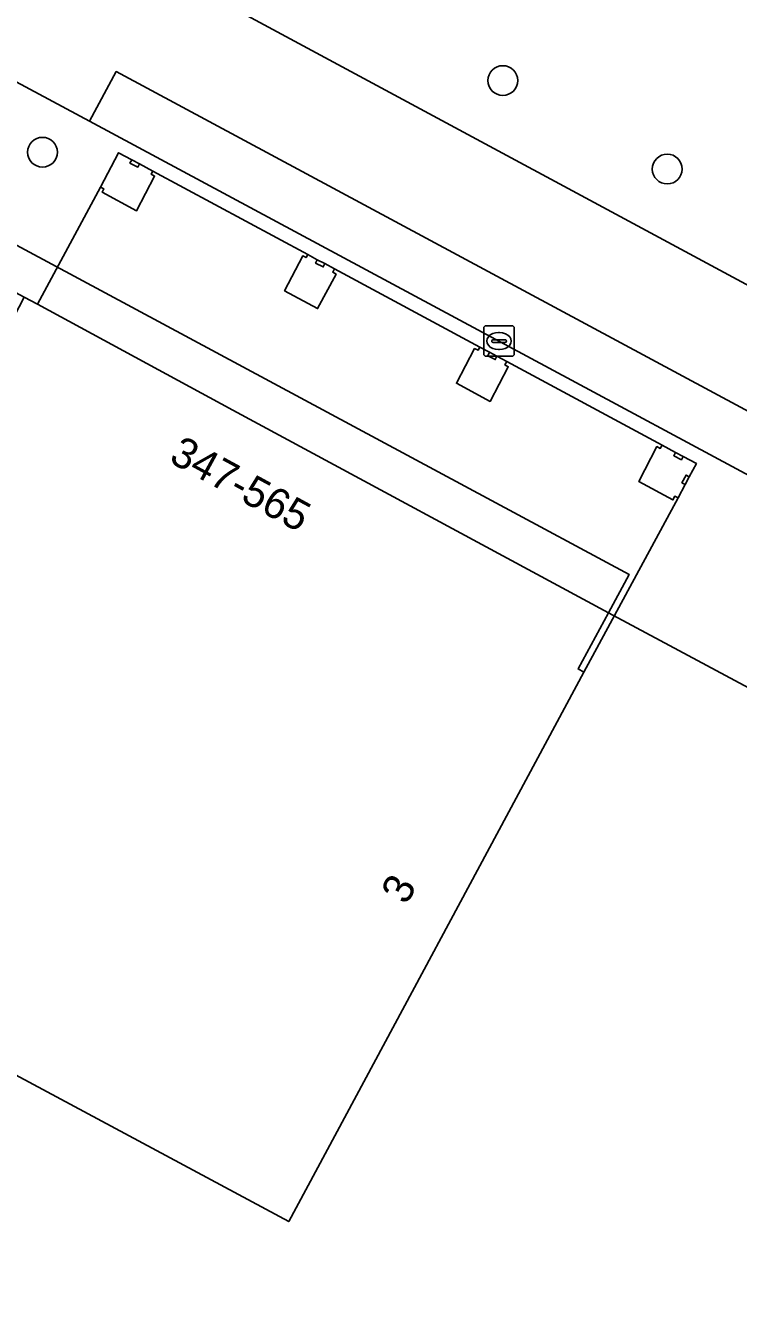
# Model space of a CAD drawing. Extents: x 159489 to 160304, y 383825 to 384531.
# Drawn here: x 159556.82 to 159580.19, y 384258.57 to 384300.92 of the extents above; entities that cross this region are included whole.
import ezdxf

# ---------------------------------------------------------------- set-up
doc = ezdxf.new("R2010")
doc.units = 0
for name, color, linetype in [('IMGEO_Boom', 7, 'Continuous'), ('IMGEO_Erf', 7, 'Continuous'), ('IMGEO_Groenvoorziening', 7, 'Continuous'), ('IMGEO_Kolk', 7, 'Continuous'), ('IMGEO_Pand', 7, 'Continuous'), ('IMGEO_Pand_nummerreeks', 7, 'Continuous'), ('IMGEO_Pand_overbouw', 7, 'Continuous'), ('IMGEO_Parkeervlak_gesloten', 7, 'Continuous'), ('IMGEO_Rijbaan_lokaal_gesloten', 7, 'Continuous'), ('IMGEO_Voetpad_open', 7, 'Continuous')]:
    doc.layers.add(name, color=color, linetype=linetype)

msp = doc.modelspace()

# ---------------------------------------------------------------- linework, layer by layer
at = {"layer": 'IMGEO_Boom'}
for centre in [(159572.468, 384299.119), (159557.37, 384296.767), (159577.86, 384296.215)]:
    msp.add_circle(centre, 0.489, dxfattribs=at)
at = {"layer": 'IMGEO_Erf'}
msp.add_lwpolyline([(159631.56, 384209.476), (159640.276, 384225.681), (159611.777, 384241.285), (159616.379, 384249.69), (159600.425, 384258.245), (159593.348, 384245.049), (159582.491, 384250.872), (159578.85, 384252.831), (159587.23, 384268.419), (159590.223, 384274), (159575.933, 384281.657), (159574.935, 384279.809), (159575.127, 384279.7), (159565.449, 384261.675), (159556.176, 384266.653), (159554.827, 384264.14), (159546.454, 384248.546), (159558.913, 384230.144), (159558.499, 384229.864), (159559.363, 384228.538), (159560.934, 384226.137), (159561.341, 384226.407), (159569.144, 384213.675)], dxfattribs=at)
at = {"layer": 'IMGEO_Groenvoorziening'}
msp.add_lwpolyline([(159534.827, 384332.312), (159520.929, 384324.852), (159521.207, 384324.29), (159525.025, 384322.248), (159542.586, 384312.826), (159546.562, 384310.695), (159582.424, 384291.365), (159580.802, 384307.588)], dxfattribs=at)
at = {"layer": 'IMGEO_Kolk'}
for p, q in [((159571.918, 384291.071), (159572.77, 384291.071)), ((159571.843, 384290.145), (159571.843, 384290.997)), ((159572.145, 384290.614), (159572.543, 384290.614)), ((159572.331, 384290.851), (159572.356, 384290.851)), ((159572.844, 384290.997), (159572.844, 384290.145)), ((159572.102, 384290.565), (159572.102, 384290.577)), ((159572.54, 384290.528), (159572.142, 384290.528)), ((159572.354, 384290.291), (159572.329, 384290.291)), ((159572.586, 384290.577), (159572.586, 384290.565)), ((159572.77, 384290.071), (159571.918, 384290.071))]:
    msp.add_line(p, q, dxfattribs=at)
for points in [[(159571.918, 384291.071), (159572.77, 384291.071)], [(159571.843, 384290.145), (159571.843, 384290.997)], [(159572.844, 384290.997), (159572.844, 384290.145)], [(159572.77, 384290.071), (159571.918, 384290.071)]]:
    msp.add_lwpolyline(points, dxfattribs=at)
for centre, radius, start, end in [((159571.92, 384290.995), 0.0765, 91.552, 178.448), ((159571.92, 384290.995), 0.0765, 91.552, 178.448), ((159572.768, 384290.995), 0.0765, 1.552, 88.448), ((159572.768, 384290.995), 0.0765, 1.552, 88.448), ((159572.142, 384290.574), 0.0403, 85.8775, 175.7526), ((159572.547, 384290.576), 0.0386, 1.7309, 96.639), ((159572.139, 384290.564), 0.0366, 178.938, 274.7102), ((159572.543, 384290.571), 0.043, 264.8664, 352.4533), ((159571.92, 384290.147), 0.0765, 181.552, 268.448), ((159571.92, 384290.147), 0.0765, 181.552, 268.448), ((159572.768, 384290.147), 0.0765, 271.552, 358.448), ((159572.768, 384290.147), 0.0765, 271.552, 358.448)]:
    msp.add_arc(centre, radius, start, end, dxfattribs=at)
for centre, major_axis, ratio, start_param, end_param in [((159572.33, 384290.571), (-0.387, 0.002), 0.722429, 4.712389, 7.853982), ((159572.355, 384290.571), (-0.39, 0.002), 0.717154, 1.570796, 4.712389)]:
    msp.add_ellipse(centre, major_axis=major_axis, ratio=ratio, start_param=start_param, end_param=end_param, dxfattribs=at)
at = {"layer": 'IMGEO_Pand'}
for points in [[(159561.044, 384295.985), (159560.936, 384296.043), (159560.994, 384296.151), (159560.556, 384296.388), (159560.498, 384296.28), (159560.239, 384296.411), (159560.296, 384296.519), (159559.868, 384296.753), (159559.275, 384295.619), (159559.382, 384295.564), (159559.324, 384295.457), (159560.456, 384294.845)], [(159566.999, 384292.769), (159566.89, 384292.829), (159566.946, 384292.937), (159566.63, 384293.113), (159566.576, 384293.004), (159566.327, 384293.131), (159566.382, 384293.24), (159566.072, 384293.416), (159566.015, 384293.31), (159565.904, 384293.366), (159565.308, 384292.224), (159566.395, 384291.637)], [(159575.127, 384279.7), (159574.935, 384279.809), (159575.933, 384281.657), (159563.611, 384288.299), (159557.204, 384291.777), (159556.766, 384292.015), (159545.068, 384269.391), (159554.827, 384264.14), (159556.176, 384266.653), (159565.449, 384261.675)], [(159572.645, 384289.73), (159572.536, 384289.787), (159572.594, 384289.895), (159572.274, 384290.073), (159572.218, 384289.961), (159571.975, 384290.09), (159572.031, 384290.202), (159571.711, 384290.375), (159571.654, 384290.27), (159571.543, 384290.325), (159570.947, 384289.184), (159572.049, 384288.588)], [(159578.819, 384286.547), (159578.384, 384286.782), (159578.327, 384286.674), (159578.074, 384286.808), (159578.134, 384286.918), (159577.69, 384287.156), (159577.633, 384287.05), (159577.522, 384287.106), (159576.926, 384285.964), (159578.044, 384285.36), (159578.109, 384285.479), (159578.215, 384285.424), (159578.446, 384285.864), (159578.339, 384285.92), (159578.477, 384286.17), (159578.582, 384286.113)]]:
    msp.add_lwpolyline(points, close=True, dxfattribs=at)
at = {"layer": 'IMGEO_Pand_overbouw'}
msp.add_lwpolyline([(159572.594, 384289.895), (159572.274, 384290.073), (159572.031, 384290.202), (159571.711, 384290.375), (159566.946, 384292.937), (159566.63, 384293.113), (159566.382, 384293.24), (159566.072, 384293.416), (159560.994, 384296.151), (159560.556, 384296.388), (159560.296, 384296.519), (159559.868, 384296.753), (159559.275, 384295.619), (159557.204, 384291.777), (159563.611, 384288.299), (159575.933, 384281.657), (159574.935, 384279.809), (159575.127, 384279.7), (159578.215, 384285.424), (159578.446, 384285.864), (159578.582, 384286.113), (159578.819, 384286.547), (159578.384, 384286.782), (159578.134, 384286.918), (159577.69, 384287.156)], close=True, dxfattribs=at)
at = {"layer": 'IMGEO_Parkeervlak_gesloten'}
msp.add_lwpolyline([(159558.914, 384297.788), (159595.94, 384277.876), (159606.009, 384272.461), (159606.884, 384274.087), (159596.815, 384279.502), (159559.789, 384299.414)], close=True, dxfattribs=at)
at = {"layer": 'IMGEO_Rijbaan_lokaal_gesloten'}
for points in [[(159643.082, 384258.763), (159632.963, 384264.225), (159584.718, 384290.116), (159582.424, 384291.365), (159546.562, 384310.695), (159542.586, 384312.826), (159525.025, 384322.248), (159521.207, 384324.29), (159504.629, 384315.388), (159502.21, 384314.104)], [(159524.477, 384316.223), (159526.867, 384315.023), (159527.963, 384314.433), (159535.565, 384310.345), (159536.44, 384311.971), (159549.851, 384304.759), (159550.324, 384304.504), (159549.449, 384302.878), (159558.914, 384297.788), (159559.789, 384299.414), (159596.815, 384279.502), (159606.884, 384274.087), (159606.009, 384272.461), (159610.125, 384270.247), (159610.999, 384271.873), (159634.42, 384259.278), (159633.545, 384257.652), (159643.266, 384252.424), (159644.14, 384254.05), (159648.99, 384251.442), (159648.115, 384249.816), (159649.108, 384249.282), (159652.612, 384247.398)]]:
    msp.add_lwpolyline(points, dxfattribs=at)
at = {"layer": 'IMGEO_Voetpad_open'}
for points in [[(159652.612, 384247.398), (159649.108, 384249.282), (159648.115, 384249.816), (159643.266, 384252.424), (159633.545, 384257.652), (159610.125, 384270.247), (159606.009, 384272.461), (159595.94, 384277.876), (159558.914, 384297.788), (159549.449, 384302.878), (159535.565, 384310.345), (159527.963, 384314.433)], [(159514.758, 384298.232), (159516.4, 384294.599), (159517.502, 384296.664), (159524.97, 384310.657), (159525.855, 384310.207), (159526.055, 384310.099), (159576.611, 384282.913), (159575.933, 384281.657), (159590.223, 384274), (159620.712, 384257.605), (159621.017, 384257.441), (159621.346, 384257.26), (159646.05, 384243.709), (159649.079, 384242.048), (159654.684, 384240.484)]]:
    msp.add_lwpolyline(points, dxfattribs=at)
for points in [[(159526.055, 384310.099), (159525.406, 384308.865), (159527.484, 384307.756), (159556.766, 384292.015), (159557.204, 384291.777), (159563.611, 384288.299), (159575.933, 384281.657), (159576.611, 384282.913)], [(159559.382, 384295.564), (159559.275, 384295.619), (159559.868, 384296.753), (159560.296, 384296.519), (159560.239, 384296.411), (159560.498, 384296.28), (159560.556, 384296.388), (159560.994, 384296.151), (159560.936, 384296.043), (159561.044, 384295.985), (159560.456, 384294.845), (159559.324, 384295.457)], [(159565.904, 384293.366), (159566.015, 384293.31), (159566.072, 384293.416), (159566.382, 384293.24), (159566.327, 384293.131), (159566.576, 384293.004), (159566.63, 384293.113), (159566.946, 384292.937), (159566.89, 384292.829), (159566.999, 384292.769), (159566.395, 384291.637), (159565.308, 384292.224)], [(159571.543, 384290.325), (159571.654, 384290.27), (159571.711, 384290.375), (159572.031, 384290.202), (159571.975, 384290.09), (159572.218, 384289.961), (159572.274, 384290.073), (159572.594, 384289.895), (159572.536, 384289.787), (159572.645, 384289.73), (159572.049, 384288.588), (159570.947, 384289.184)], [(159577.69, 384287.156), (159578.134, 384286.918), (159578.074, 384286.808), (159578.327, 384286.674), (159578.384, 384286.782), (159578.819, 384286.547), (159578.582, 384286.113), (159578.477, 384286.17), (159578.339, 384285.92), (159578.446, 384285.864), (159578.215, 384285.424), (159578.109, 384285.479), (159578.044, 384285.36), (159576.926, 384285.964), (159577.522, 384287.106), (159577.633, 384287.05)]]:
    msp.add_lwpolyline(points, close=True, dxfattribs=at)

# ---------------------------------------------------------------- texts
at = {"layer": 'IMGEO_Pand_nummerreeks'}
for s, rotation, p in [('347-565', 331.4782, (159561.48, 384286.62)), ('3', 61.57, (159569.309, 384272.038))]:
    msp.add_text(s, height=1, rotation=rotation, dxfattribs=at).set_placement(p)

doc.saveas('drawing.dxf')
